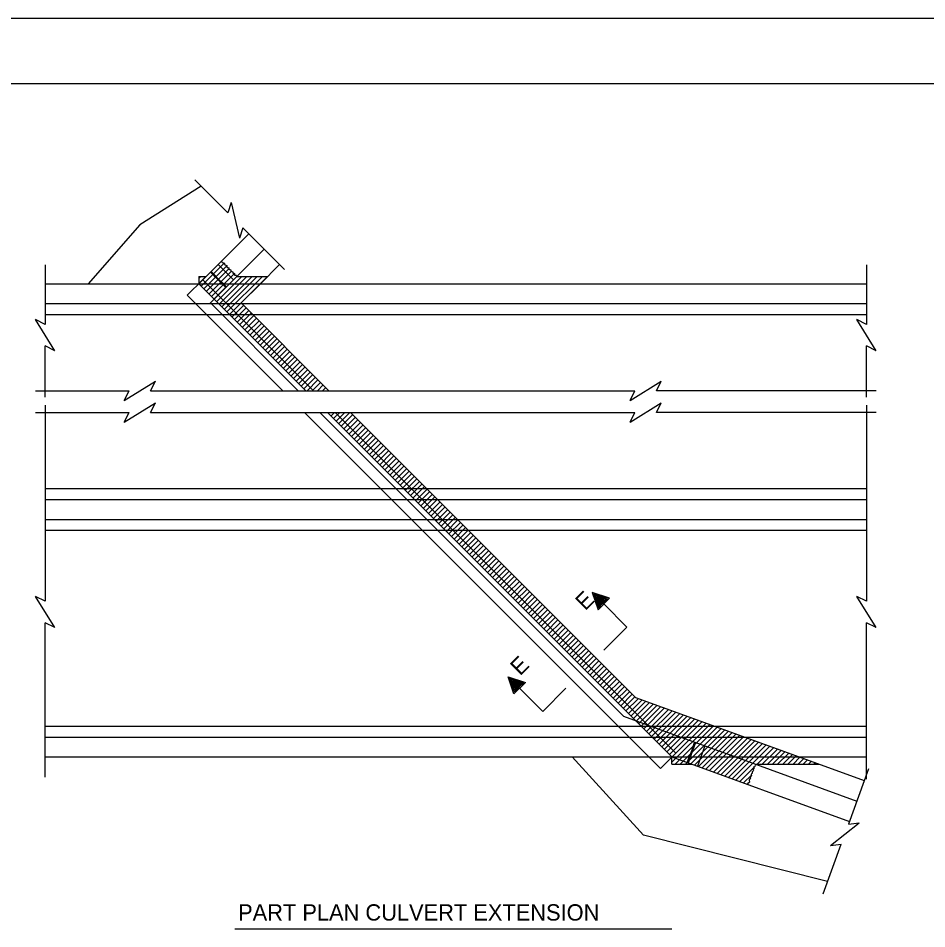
# Model space of a CAD drawing. Extents: x -0.08 to 2.83, y -0.03 to 1.92.
# Drawn here: x 0.718 to 1.588, y 0.961 to 1.833 of the extents above; entities that cross this region are included whole.
import ezdxf

# ---------------------------------------------------------------- set-up
doc = ezdxf.new("R2010")
doc.units = 0
for name, color, linetype in [('50', 7, 'Continuous'), ('55', 7, 'Continuous'), ('57', 7, 'Continuous'), ('63', 7, 'Continuous')]:
    doc.layers.add(name, color=color, linetype=linetype)

msp = doc.modelspace()

# ---------------------------------------------------------------- linework, layer by layer
at = {"layer": '50'}
for p, q in [((0.89336, 1.67253), (0.83473, 1.63561)), ((0.83473, 1.63561), (0.78529, 1.57914)), ((0.8912, 1.57914), (0.93897, 1.62692)), ((0.92066, 1.57914), (0.9537, 1.61218)), ((0.92434, 1.58282), (0.90961, 1.59756)), ((0.95012, 1.57914), (0.96843, 1.59745)), ((0.90635, 1.58609), (0.90224, 1.59019)), ((0.91728, 1.57577), (0.90255, 1.5905)), ((0.90713, 1.58653), (0.90286, 1.5908)), ((0.7441, 1.57914), (0.8912, 1.57914)), ((0.88015, 1.56809), (0.89488, 1.58282)), ((0.99363, 1.47671), (0.8912, 1.57914)), ((0.8912, 1.57914), (0.89856, 1.57914)), ((1.00099, 1.47671), (0.89488, 1.58282)), ((0.89856, 1.57914), (1.53056, 1.57914)), ((0.91698, 1.57546), (0.90635, 1.58609)), ((0.91759, 1.57607), (0.90758, 1.58609)), ((0.90961, 1.56809), (0.92066, 1.57914)), ((0.93171, 1.56073), (0.95012, 1.57914)), ((0.97153, 1.47671), (0.88015, 1.56809)), ((0.90156, 1.56004), (0.90961, 1.56809)), ((0.98626, 1.47671), (0.90224, 1.56073)), ((1.01572, 1.47671), (0.93171, 1.56073)), ((0.7441, 1.56004), (1.53056, 1.56004)), ((0.7441, 1.54963), (1.53056, 1.54963)), ((1.33327, 1.11497), (0.99236, 1.45588)), ((1.29788, 1.16509), (1.00709, 1.45588)), ((1.34432, 1.12602), (1.01446, 1.45588)), ((1.348, 1.1297), (1.02183, 1.45588)), ((1.30935, 1.18309), (1.03656, 1.45588)), ((0.7441, 1.38296), (1.53056, 1.38296)), ((0.7441, 1.37254), (1.53056, 1.37254)), ((0.7441, 1.35345), (1.53056, 1.35345)), ((0.7441, 1.34303), (1.53056, 1.34303)), ((1.30935, 1.18309), (1.46615, 1.12602)), ((1.29788, 1.16509), (1.35276, 1.14511)), ((0.7441, 1.15553), (1.53056, 1.15553)), ((0.7441, 1.14511), (1.53056, 1.14511)), ((1.35276, 1.14511), (1.40523, 1.12602)), ((1.36613, 1.14025), (1.359, 1.12067)), ((1.36654, 1.1401), (1.35941, 1.12052)), ((1.36694, 1.13995), (1.35982, 1.12038)), ((1.37592, 1.13669), (1.36879, 1.11711)), ((0.7441, 1.12602), (1.34432, 1.12602)), ((1.31701, 1.05097), (1.24883, 1.12602)), ((1.33327, 1.11497), (1.348, 1.1297)), ((1.34432, 1.12602), (1.53056, 1.12602)), ((1.34432, 1.12602), (1.51416, 1.0642)), ((1.40523, 1.12602), (1.52129, 1.08378)), ((1.46615, 1.12602), (1.52841, 1.10335)), ((1.49329, 1.00685), (1.31701, 1.05097))]:
    msp.add_line(p, q, dxfattribs=at)
for points in [[(0.90541, 1.58822), (0.90326, 1.59036), (0.90269, 1.58979), (0.90483, 1.58764)], [(0.90755, 1.58607), (0.90541, 1.58822), (0.90483, 1.58764), (0.90698, 1.5855)], [(0.91507, 1.57856), (0.91292, 1.5807), (0.91235, 1.58013), (0.91449, 1.57798)], [(0.91721, 1.57641), (0.91507, 1.57856), (0.91449, 1.57798), (0.91664, 1.57584)], [(1.36571, 1.13663), (1.36467, 1.13378), (1.36391, 1.13406), (1.36494, 1.13691)], [(1.36675, 1.13949), (1.36571, 1.13663), (1.36494, 1.13691), (1.36598, 1.13976)], [(1.36207, 1.12665), (1.36103, 1.1238), (1.36027, 1.12407), (1.36131, 1.12692)], [(1.36103, 1.1238), (1.36, 1.12094), (1.35923, 1.12122), (1.36027, 1.12407)]]:
    msp.add_lwpolyline(points, close=True, dxfattribs=at)
at = {"layer": '55'}
for p, q in [((0.88734, 1.67855), (0.91881, 1.64708)), ((0.92208, 1.65688), (0.91881, 1.64708)), ((0.92208, 1.65688), (0.93009, 1.62271)), ((0.93337, 1.63252), (0.93009, 1.62271)), ((0.97311, 1.59278), (0.93337, 1.63252)), ((0.7441, 1.59719), (0.7441, 1.54018)), ((0.89357, 1.57676), (0.91525, 1.59844)), ((0.89603, 1.57431), (0.91771, 1.59598)), ((1.53056, 1.59719), (1.53056, 1.54018)), ((0.89848, 1.57185), (0.92016, 1.59353)), ((0.90094, 1.5694), (0.92262, 1.59107)), ((0.90339, 1.56694), (0.92507, 1.58862)), ((0.8912, 1.58609), (0.8912, 1.57914)), ((0.8912, 1.58421), (0.89308, 1.58609)), ((0.8912, 1.5793), (0.89799, 1.58609)), ((0.8912, 1.58609), (0.89814, 1.58609)), ((0.90585, 1.56449), (0.92753, 1.58616)), ((0.90831, 1.56203), (0.93236, 1.58609)), ((0.91076, 1.55958), (0.93727, 1.58609)), ((0.91322, 1.55712), (0.94218, 1.58609)), ((0.91567, 1.55467), (0.94709, 1.58609)), ((0.91813, 1.55221), (0.952, 1.58609)), ((0.92058, 1.54976), (0.95691, 1.58609)), ((0.9276, 1.58609), (0.95707, 1.58609)), ((0.92304, 1.5473), (0.93409, 1.55835)), ((0.92549, 1.54484), (0.93654, 1.55589)), ((0.92795, 1.54239), (0.939, 1.55344)), ((0.7441, 1.54018), (0.73485, 1.5448)), ((0.75334, 1.51496), (0.73485, 1.5448)), ((0.9304, 1.53993), (0.94145, 1.55098)), ((0.93286, 1.53748), (0.94391, 1.54853)), ((0.93531, 1.53502), (0.94636, 1.54607)), ((0.93777, 1.53257), (0.94882, 1.54362)), ((1.53056, 1.54018), (1.5213, 1.5448)), ((1.5398, 1.51496), (1.5213, 1.5448)), ((0.94022, 1.53011), (0.95127, 1.54116)), ((0.94268, 1.52766), (0.95373, 1.53871)), ((0.94513, 1.5252), (0.95618, 1.53625)), ((0.94759, 1.52275), (0.95864, 1.5338)), ((0.95004, 1.52029), (0.96109, 1.53134)), ((0.9525, 1.51784), (0.96355, 1.52889)), ((0.95495, 1.51538), (0.966, 1.52643)), ((0.7441, 1.47047), (0.7441, 1.51959)), ((0.75334, 1.51496), (0.7441, 1.51959)), ((0.95741, 1.51293), (0.96846, 1.52398)), ((0.95987, 1.51047), (0.97091, 1.52152)), ((0.96232, 1.50802), (0.97337, 1.51906)), ((1.53056, 1.47047), (1.53056, 1.51959)), ((1.5398, 1.51496), (1.53056, 1.51959)), ((0.96478, 1.50556), (0.97582, 1.51661)), ((0.96723, 1.50311), (0.97828, 1.51415)), ((0.96969, 1.50065), (0.98073, 1.5117)), ((0.97214, 1.4982), (0.98319, 1.50924)), ((0.9746, 1.49574), (0.98565, 1.50679)), ((0.97705, 1.49328), (0.9881, 1.50433)), ((0.97951, 1.49083), (0.99056, 1.50188)), ((0.98196, 1.48837), (0.99301, 1.49942)), ((0.98442, 1.48592), (0.99547, 1.49697)), ((0.98687, 1.48346), (0.99792, 1.49451)), ((0.98933, 1.48101), (1.00038, 1.49206)), ((0.81972, 1.46746), (0.84955, 1.48596)), ((0.84493, 1.47671), (0.84955, 1.48596)), ((0.99178, 1.47855), (1.00283, 1.4896)), ((0.99485, 1.47671), (1.00529, 1.48715)), ((0.99976, 1.47671), (1.00774, 1.48469)), ((1.00467, 1.47671), (1.0102, 1.48224)), ((1.3042, 1.46746), (1.33404, 1.48596)), ((1.32942, 1.47671), (1.33404, 1.48596)), ((0.73485, 1.47671), (0.82434, 1.47671)), ((0.81972, 1.46746), (0.82434, 1.47671)), ((0.84493, 1.47671), (1.30883, 1.47671)), ((1.00958, 1.47671), (1.01265, 1.47978)), ((1.01449, 1.47671), (1.01511, 1.47733)), ((1.3042, 1.46746), (1.30883, 1.47671)), ((1.5398, 1.47671), (1.32942, 1.47671)), ((0.81972, 1.44663), (0.84955, 1.46513)), ((0.84493, 1.45588), (0.84955, 1.46513)), ((1.3042, 1.44663), (1.33404, 1.46513)), ((1.32942, 1.45588), (1.33404, 1.46513)), ((0.7441, 1.46276), (0.7441, 1.27503)), ((1.53056, 1.46276), (1.53056, 1.27503)), ((0.73485, 1.45588), (0.82434, 1.45588)), ((0.81972, 1.44663), (0.82434, 1.45588)), ((0.84493, 1.45588), (1.30883, 1.45588)), ((1.01537, 1.45497), (1.01628, 1.45588)), ((1.01782, 1.45251), (1.02119, 1.45588)), ((1.02028, 1.45006), (1.0261, 1.45588)), ((1.02273, 1.4476), (1.03101, 1.45588)), ((1.02519, 1.44515), (1.03592, 1.45588)), ((1.02764, 1.44269), (1.03869, 1.45374)), ((1.0301, 1.44024), (1.04115, 1.45129)), ((1.03256, 1.43778), (1.0436, 1.44883)), ((1.3042, 1.44663), (1.30883, 1.45588)), ((1.5398, 1.45588), (1.32942, 1.45588)), ((1.03501, 1.43533), (1.04606, 1.44638)), ((1.03747, 1.43287), (1.04851, 1.44392)), ((1.03992, 1.43042), (1.05097, 1.44146)), ((1.04238, 1.42796), (1.05342, 1.43901)), ((1.04483, 1.42551), (1.05588, 1.43655)), ((1.04729, 1.42305), (1.05833, 1.4341)), ((1.04974, 1.4206), (1.06079, 1.43164)), ((1.0522, 1.41814), (1.06325, 1.42919)), ((1.05465, 1.41568), (1.0657, 1.42673)), ((1.05711, 1.41323), (1.06816, 1.42428)), ((1.05956, 1.41077), (1.07061, 1.42182)), ((1.06202, 1.40832), (1.07307, 1.41937)), ((1.06447, 1.40586), (1.07552, 1.41691)), ((1.06693, 1.40341), (1.07798, 1.41446)), ((1.06938, 1.40095), (1.08043, 1.412)), ((1.07184, 1.3985), (1.08289, 1.40955)), ((1.07429, 1.39604), (1.08534, 1.40709)), ((1.07675, 1.39359), (1.0878, 1.40464)), ((1.0792, 1.39113), (1.09025, 1.40218)), ((1.08166, 1.38868), (1.09271, 1.39973)), ((1.08411, 1.38622), (1.09516, 1.39727)), ((1.08657, 1.38377), (1.09762, 1.39482)), ((1.08903, 1.38131), (1.10007, 1.39236)), ((1.09148, 1.37886), (1.10253, 1.3899)), ((1.09394, 1.3764), (1.10498, 1.38745)), ((1.09639, 1.37395), (1.10744, 1.38499)), ((1.09885, 1.37149), (1.10989, 1.38254)), ((1.1013, 1.36904), (1.11235, 1.38008)), ((1.10376, 1.36658), (1.11481, 1.37763)), ((1.10621, 1.36412), (1.11726, 1.37517)), ((1.10867, 1.36167), (1.11972, 1.37272)), ((1.11112, 1.35921), (1.12217, 1.37026)), ((1.11358, 1.35676), (1.12463, 1.36781)), ((1.11603, 1.3543), (1.12708, 1.36535)), ((1.11849, 1.35185), (1.12954, 1.3629)), ((1.12094, 1.34939), (1.13199, 1.36044)), ((1.1234, 1.34694), (1.13445, 1.35799)), ((1.12585, 1.34448), (1.1369, 1.35553)), ((1.12831, 1.34203), (1.13936, 1.35308)), ((1.13076, 1.33957), (1.14181, 1.35062)), ((1.13322, 1.33712), (1.14427, 1.34817)), ((1.13567, 1.33466), (1.14672, 1.34571)), ((1.13813, 1.33221), (1.14918, 1.34326)), ((1.14059, 1.32975), (1.15163, 1.3408)), ((1.14304, 1.3273), (1.15409, 1.33834)), ((1.1455, 1.32484), (1.15654, 1.33589)), ((1.14795, 1.32239), (1.159, 1.33343)), ((1.15041, 1.31993), (1.16145, 1.33098)), ((1.15286, 1.31748), (1.16391, 1.32852)), ((1.15532, 1.31502), (1.16637, 1.32607)), ((1.15777, 1.31256), (1.16882, 1.32361)), ((1.16023, 1.31011), (1.17128, 1.32116)), ((1.16268, 1.30765), (1.17373, 1.3187)), ((1.16514, 1.3052), (1.17619, 1.31625)), ((1.16759, 1.30274), (1.17864, 1.31379)), ((1.17005, 1.30029), (1.1811, 1.31134)), ((1.1725, 1.29783), (1.18355, 1.30888)), ((1.17496, 1.29538), (1.18601, 1.30643)), ((1.17741, 1.29292), (1.18846, 1.30397)), ((1.17987, 1.29047), (1.19092, 1.30152)), ((1.18232, 1.28801), (1.19337, 1.29906)), ((1.18478, 1.28556), (1.19583, 1.29661)), ((1.18723, 1.2831), (1.19828, 1.29415)), ((1.18969, 1.28065), (1.20074, 1.2917)), ((1.19215, 1.27819), (1.20319, 1.28924)), ((1.1946, 1.27574), (1.20565, 1.28679)), ((1.19706, 1.27328), (1.2081, 1.28433)), ((1.19951, 1.27083), (1.21056, 1.28187)), ((0.7441, 1.27503), (0.73485, 1.27965)), ((0.75334, 1.24982), (0.73485, 1.27965)), ((1.20197, 1.26837), (1.21301, 1.27942)), ((1.20442, 1.26592), (1.21547, 1.27696)), ((1.20688, 1.26346), (1.21793, 1.27451)), ((1.53056, 1.27503), (1.5213, 1.27965)), ((1.5398, 1.24982), (1.5213, 1.27965)), ((1.20933, 1.26101), (1.22038, 1.27205)), ((1.21179, 1.25855), (1.22284, 1.2696)), ((1.21424, 1.25609), (1.22529, 1.26714)), ((1.2167, 1.25364), (1.22775, 1.26469)), ((1.21915, 1.25118), (1.2302, 1.26223)), ((1.22161, 1.24873), (1.23266, 1.25978)), ((1.22406, 1.24627), (1.23511, 1.25732)), ((0.7441, 1.10659), (0.7441, 1.25445)), ((0.75334, 1.24982), (0.7441, 1.25445)), ((1.22652, 1.24382), (1.23757, 1.25487)), ((1.22897, 1.24136), (1.24002, 1.25241)), ((1.23143, 1.23891), (1.24248, 1.24996)), ((1.23388, 1.23645), (1.24493, 1.2475)), ((1.53056, 1.10488), (1.53056, 1.25445)), ((1.5398, 1.24982), (1.53056, 1.25445)), ((1.23634, 1.234), (1.24739, 1.24505)), ((1.23879, 1.23154), (1.24984, 1.24259)), ((1.24125, 1.22909), (1.2523, 1.24014)), ((1.24371, 1.22663), (1.25475, 1.23768)), ((1.24616, 1.22418), (1.25721, 1.23523)), ((1.24862, 1.22172), (1.25966, 1.23277)), ((1.25107, 1.21927), (1.26212, 1.23031)), ((1.25353, 1.21681), (1.26457, 1.22786)), ((1.25598, 1.21436), (1.26703, 1.2254)), ((1.25844, 1.2119), (1.26948, 1.22295)), ((1.26089, 1.20945), (1.27194, 1.22049)), ((1.26335, 1.20699), (1.2744, 1.21804)), ((1.2658, 1.20453), (1.27685, 1.21558)), ((1.26826, 1.20208), (1.27931, 1.21313)), ((1.27071, 1.19962), (1.28176, 1.21067)), ((1.27317, 1.19717), (1.28422, 1.20822)), ((1.27562, 1.19471), (1.28667, 1.20576)), ((1.27808, 1.19226), (1.28913, 1.20331)), ((1.28053, 1.1898), (1.29158, 1.20085)), ((1.28299, 1.18735), (1.29404, 1.1984)), ((1.28544, 1.18489), (1.29649, 1.19594)), ((1.2879, 1.18244), (1.29895, 1.19349)), ((1.29035, 1.17998), (1.3014, 1.19103)), ((1.29281, 1.17753), (1.30386, 1.18858)), ((1.29526, 1.17507), (1.30631, 1.18612)), ((1.29772, 1.17262), (1.30877, 1.18367)), ((1.30018, 1.17016), (1.3121, 1.18208)), ((1.30263, 1.16771), (1.3157, 1.18077)), ((1.30509, 1.16525), (1.3193, 1.17946)), ((1.30754, 1.1628), (1.3229, 1.17815)), ((1.31, 1.16034), (1.3265, 1.17684)), ((1.31245, 1.15789), (1.3301, 1.17553)), ((1.31491, 1.15543), (1.3337, 1.17422)), ((1.31736, 1.15297), (1.3373, 1.17291)), ((1.31982, 1.15052), (1.3409, 1.1716)), ((1.32227, 1.14806), (1.3445, 1.17029)), ((1.32473, 1.14561), (1.3481, 1.16898)), ((1.32718, 1.14315), (1.3517, 1.16767)), ((1.32964, 1.1407), (1.3553, 1.16636)), ((1.33209, 1.13824), (1.3589, 1.16505)), ((1.33455, 1.13579), (1.3625, 1.16374)), ((1.337, 1.13333), (1.3661, 1.16243)), ((1.33946, 1.13088), (1.3697, 1.16112)), ((1.34191, 1.12842), (1.3733, 1.15981)), ((1.34432, 1.12592), (1.3769, 1.1585)), ((1.34432, 1.12101), (1.3805, 1.15719)), ((1.34729, 1.11907), (1.3841, 1.15588)), ((1.35221, 1.11907), (1.3877, 1.15457)), ((1.35712, 1.11907), (1.3913, 1.15326)), ((1.36203, 1.11907), (1.3949, 1.15195)), ((1.36599, 1.11813), (1.3985, 1.15064)), ((1.36959, 1.11682), (1.4021, 1.14933)), ((1.37319, 1.11551), (1.4057, 1.14802)), ((1.37679, 1.1142), (1.4093, 1.14671)), ((1.38039, 1.11289), (1.4129, 1.1454)), ((1.38399, 1.11158), (1.4165, 1.14408)), ((1.38759, 1.11027), (1.4201, 1.14277)), ((1.39119, 1.10896), (1.4237, 1.14146)), ((1.39479, 1.10765), (1.4273, 1.14015)), ((1.39839, 1.10633), (1.4309, 1.13884)), ((1.40199, 1.10502), (1.4345, 1.13753)), ((1.40559, 1.10371), (1.4381, 1.13622)), ((1.42586, 1.11907), (1.4417, 1.13491)), ((1.43077, 1.11907), (1.4453, 1.1336)), ((1.34432, 1.11907), (1.34432, 1.12602)), ((1.43568, 1.11907), (1.4489, 1.13229)), ((1.44059, 1.11907), (1.4525, 1.13098)), ((1.4455, 1.11907), (1.4561, 1.12967)), ((1.45041, 1.11907), (1.4597, 1.12836)), ((1.45532, 1.11907), (1.4633, 1.12705)), ((1.46024, 1.11907), (1.4669, 1.12574)), ((1.34432, 1.11907), (1.3634, 1.11907)), ((1.40919, 1.1024), (1.42309, 1.1163)), ((1.42431, 1.11907), (1.48523, 1.11907)), ((1.46515, 1.11907), (1.4705, 1.12443)), ((1.47006, 1.11907), (1.4741, 1.12312)), ((1.47497, 1.11907), (1.4777, 1.12181)), ((1.47988, 1.11907), (1.4813, 1.1205)), ((1.48479, 1.11907), (1.4849, 1.11919)), ((1.41279, 1.10109), (1.42062, 1.10892)), ((1.53248, 1.11453), (1.51329, 1.06179)), ((1.41639, 1.09978), (1.41719, 1.10058)), ((1.49598, 1.04125), (1.52355, 1.06298)), ((1.51327, 1.06179), (1.52355, 1.06298)), ((1.489, 0.99507), (1.50624, 1.04244)), ((1.49598, 1.04125), (1.50624, 1.04244))]:
    msp.add_line(p, q, dxfattribs=at)
for points in [[(1.27913, 1.22827), (1.30122, 1.25037), (1.27913, 1.27247), (1.28459, 1.27793), (1.26802, 1.28346), (1.27354, 1.26688), (1.27905, 1.27238), (1.2783, 1.27329), (1.28265, 1.27763), (1.26939, 1.28205), (1.27381, 1.26879), (1.27822, 1.27321), (1.27764, 1.27395), (1.28109, 1.2774), (1.27048, 1.28093), (1.27402, 1.27033), (1.27756, 1.27387), (1.27698, 1.27461), (1.27943, 1.27706), (1.27196, 1.27954), (1.27445, 1.27208), (1.2769, 1.27453), (1.27629, 1.2753), (1.27801, 1.27702), (1.27275, 1.27877), (1.2745, 1.27351), (1.27621, 1.27522), (1.27589, 1.2757), (1.27688, 1.27669), (1.27382, 1.27772), (1.27484, 1.27465), (1.27581, 1.27562), (1.2755, 1.2761), (1.27587, 1.27647), (1.27473, 1.27685), (1.27511, 1.27571), (1.27542, 1.27601)], [(1.24262, 1.19176), (1.22052, 1.16967), (1.19842, 1.19176), (1.19296, 1.1863), (1.18743, 1.20287), (1.20401, 1.19735), (1.19851, 1.19184), (1.1976, 1.19259), (1.19326, 1.18824), (1.18884, 1.2015), (1.20209, 1.19708), (1.19768, 1.19267), (1.19694, 1.19325), (1.19349, 1.1898), (1.18996, 1.20041), (1.20056, 1.19687), (1.19702, 1.19333), (1.19628, 1.19391), (1.19383, 1.19146), (1.19135, 1.19893), (1.19881, 1.19644), (1.19636, 1.19399), (1.19559, 1.1946), (1.19387, 1.19288), (1.19212, 1.19814), (1.19738, 1.19639), (1.19567, 1.19468), (1.19519, 1.195), (1.1942, 1.19401), (1.19317, 1.19707), (1.19624, 1.19605), (1.19527, 1.19508), (1.19479, 1.19539), (1.19442, 1.19502), (1.19404, 1.19616), (1.19518, 1.19578), (1.19488, 1.19547)]]:
    msp.add_lwpolyline(points, dxfattribs=at)
for points in [[(0.91287, 1.60082), (0.91355, 1.59935), (0.91536, 1.59908), (0.91603, 1.59708), (0.9179, 1.59641), (0.91817, 1.59474), (0.91991, 1.5944), (0.92004, 1.593), (0.92144, 1.59273), (0.92191, 1.59106), (0.92358, 1.59073), (0.92379, 1.58932), (0.92532, 1.58885), (0.92539, 1.58745), (0.92693, 1.58738), (0.9276, 1.58609)], [(1.41719, 1.09949), (1.41719, 1.10111), (1.41871, 1.10212), (1.41847, 1.10422), (1.41988, 1.10561), (1.41942, 1.10724), (1.42085, 1.10828), (1.42038, 1.10961), (1.42154, 1.11045), (1.42126, 1.11216), (1.42263, 1.11317), (1.42222, 1.11453), (1.42342, 1.1156), (1.42288, 1.1169), (1.42425, 1.11761), (1.42431, 1.11907)]]:
    msp.add_spline(points, degree=3, dxfattribs=at)
at = {"layer": '57'}
msp.add_line((0.92563, 0.96151), (1.34417, 0.96151), dxfattribs=at)
at = {"layer": '63'}
msp.add_line((0, 1.83333), (2.83333, 1.83333), dxfattribs=at)
msp.add_lwpolyline([(0.16668, 0.06244), (0.16668, 1.77077), (2.72918, 1.77077), (2.72918, 0.10411), (2.56251, 0.10411), (2.56251, 0.14578), (2.07387, 0.14578), (2.07387, 0.06244)], close=True, dxfattribs=at)

# ---------------------------------------------------------------- texts
at = {"layer": '57'}
for p in [(1.26125, 1.26542), (1.19893, 1.20309)]:
    msp.add_text('E', height=0.01562, rotation=45, dxfattribs=at).set_placement(p)
msp.add_text('PART PLAN CULVERT EXTENSION', height=0.015625, dxfattribs=at).set_placement((0.92879, 0.96933))

doc.saveas('drawing.dxf')
